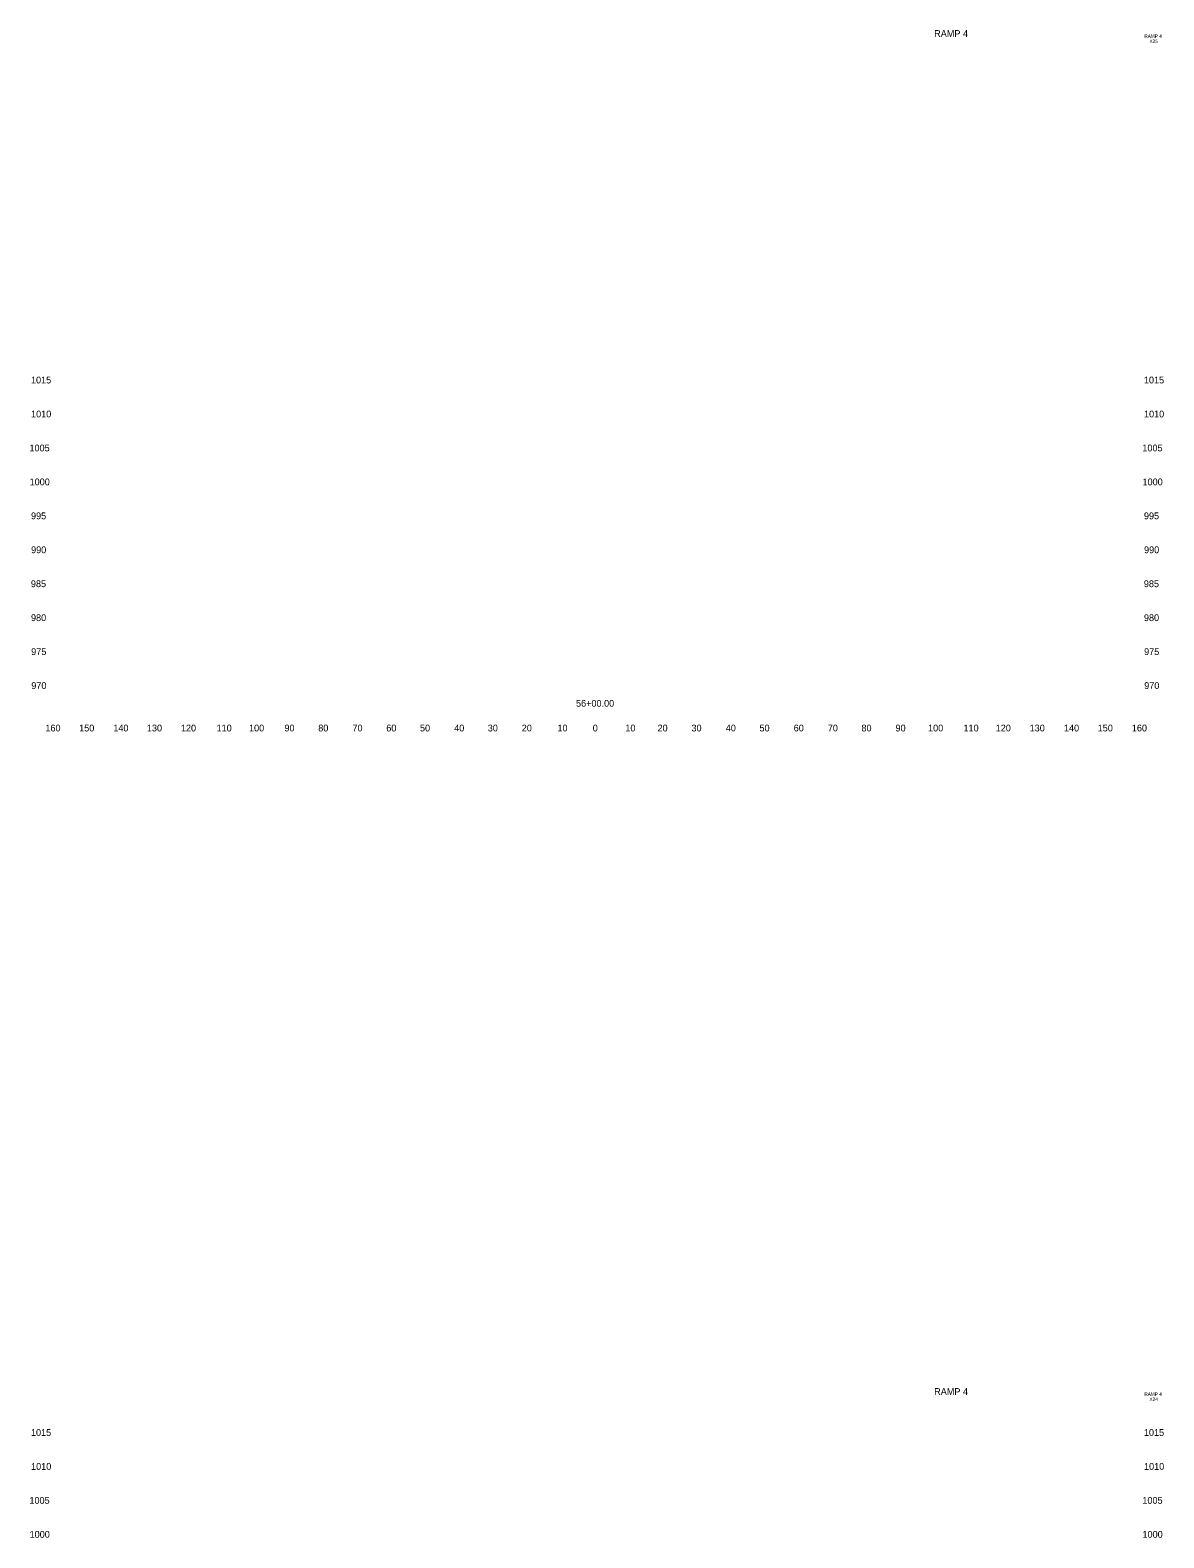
# Model space of a CAD drawing. Extents: x 4994 to 6872, y 4997 to 8804.
# Drawn here: x 6023.6 to 6357.5, y 6360 to 6804.1 of the extents above; entities that cross this region are included whole.
import ezdxf

# ---------------------------------------------------------------- set-up
doc = ezdxf.new("R2010")
doc.units = 0
for name, color, linetype in [('RD_SHT_ID', 7, 'Continuous'), ('RD_XS_TX_Offset', 7, 'Continuous'), ('RD_XS_TX_Station', 7, 'Continuous')]:
    doc.layers.add(name, color=color, linetype=linetype)

msp = doc.modelspace()

# ---------------------------------------------------------------- texts
at = {"layer": 'RD_SHT_ID'}
for s, height, p in [('RAMP 4', 2, (6289.88, 6802.06)), ('RAMP 4', 1, (6351.78, 6801.8)), ('X25', 1, (6353.29, 6800.3)), ('RAMP 4', 2, (6289.88, 6402.06)), ('RAMP 4', 1, (6351.78, 6401.8)), ('X24', 1, (6353.29, 6400.3))]:
    msp.add_text(s, height=height, dxfattribs=at).set_placement(p)
at = {"layer": 'RD_XS_TX_Offset'}
for s, p in [('1015', (6023.85, 6700)), ('1015', (6351.65, 6700)), ('1010', (6023.88, 6690)), ('1010', (6351.68, 6690)), ('1005', (6023.4, 6680)), ('1005', (6351.2, 6680)), ('1000', (6023.44, 6670)), ('1000', (6351.24, 6670)), ('995', (6023.86, 6660)), ('995', (6351.66, 6660)), ('990', (6023.89, 6650)), ('990', (6351.69, 6650)), ('985', (6023.83, 6640)), ('985', (6351.63, 6640)), ('980', (6023.86, 6630)), ('980', (6351.66, 6630)), ('975', (6023.91, 6620)), ('975', (6351.71, 6620)), ('970', (6023.94, 6610)), ('970', (6351.74, 6610)), ('160', (6028.1, 6597.5)), ('150', (6038.04, 6597.5)), ('140', (6048.1, 6597.5)), ('130', (6057.99, 6597.5)), ('120', (6068.01, 6597.5)), ('110', (6078.51, 6597.5)), ('100', (6088.07, 6597.5)), ('90', (6098.5, 6597.5)), ('80', (6108.46, 6597.5)), ('70', (6118.54, 6597.5)), ('60', (6128.5, 6597.5)), ('50', (6138.43, 6597.5)), ('40', (6148.5, 6597.5)), ('30', (6158.39, 6597.5)), ('20', (6168.4, 6597.5)), ('10', (6178.91, 6597.5)), ('0', (6189.3, 6597.5)), ('0', (6189.3, 6597.5)), ('10', (6198.91, 6597.5)), ('20', (6208.4, 6597.5)), ('30', (6218.39, 6597.5)), ('40', (6228.5, 6597.5)), ('50', (6238.43, 6597.5)), ('60', (6248.5, 6597.5)), ('70', (6258.54, 6597.5)), ('80', (6268.46, 6597.5)), ('90', (6278.5, 6597.5)), ('100', (6288.07, 6597.5)), ('110', (6298.51, 6597.5)), ('120', (6308.01, 6597.5)), ('130', (6317.99, 6597.5)), ('140', (6328.1, 6597.5)), ('150', (6338.04, 6597.5)), ('160', (6348.1, 6597.5)), ('1015', (6023.85, 6390)), ('1015', (6351.65, 6390)), ('1010', (6023.88, 6380)), ('1010', (6351.68, 6380)), ('1005', (6023.4, 6370)), ('1005', (6351.2, 6370)), ('1000', (6023.44, 6360)), ('1000', (6351.24, 6360))]:
    msp.add_text(s, height=2, dxfattribs=at).set_placement(p)
at = {"layer": 'RD_XS_TX_Station'}
msp.add_text('56+00.00', height=2, dxfattribs=at).set_placement((6184.39, 6604.78))

doc.saveas('drawing.dxf')
